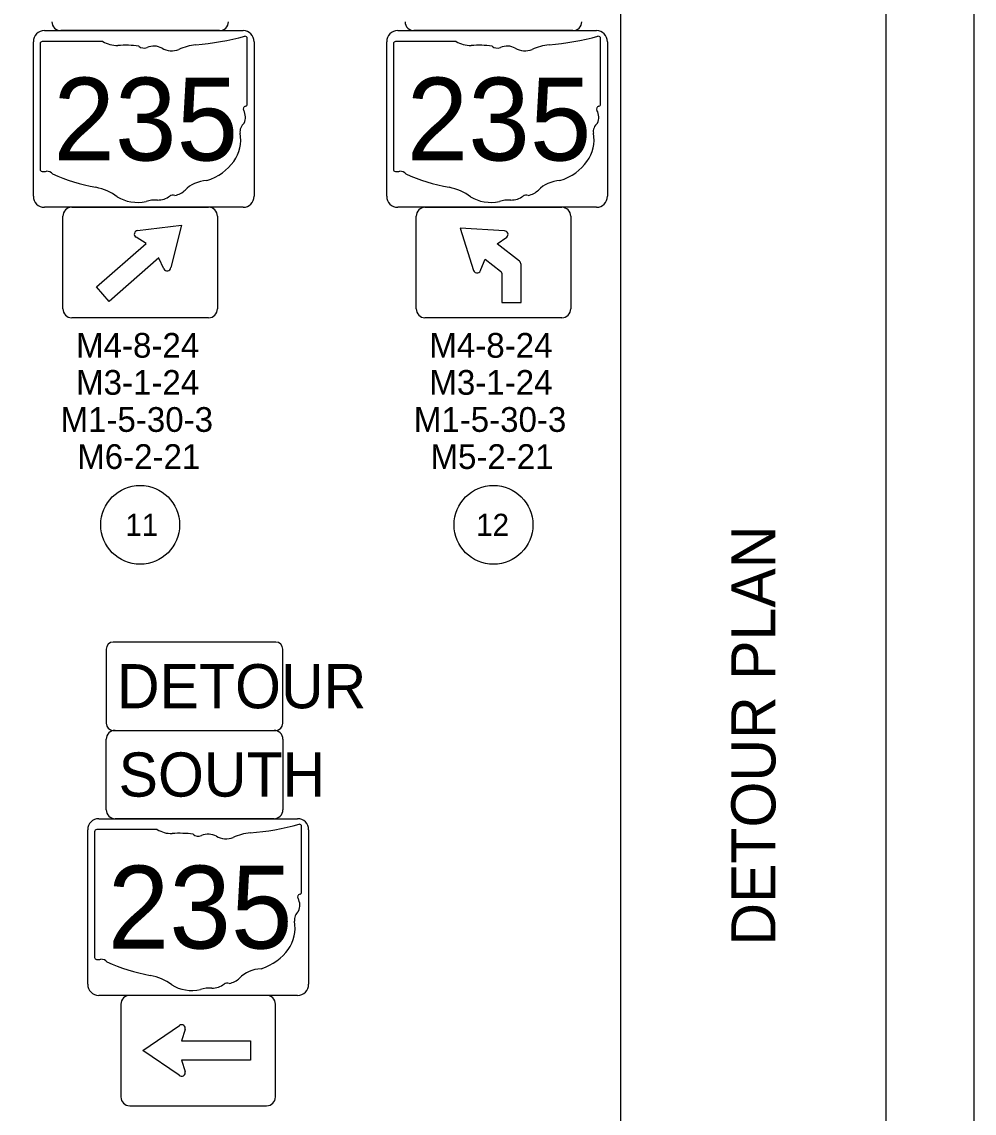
# Model space of a CAD drawing. Extents: x 632.2 to 666.2, y -36.3 to -14.3.
# Drawn here: x 660.8 to 666.19, y -25.48 to -19.3 of the extents above; entities that cross this region are included whole.
import ezdxf

# ---------------------------------------------------------------- set-up
doc = ezdxf.new("R2010")
doc.units = 0
for name, color, linetype in [('Default', 7, 'Continuous'), ('SH_Border', 7, 'Continuous'), ('SH_Cut_Line', 7, 'Continuous'), ('SH_Data', 7, 'Continuous'), ('SN_P_Signs', 7, 'Continuous'), ('SN_P_Text', 7, 'Continuous')]:
    doc.layers.add(name, color=color, linetype=linetype)

msp = doc.modelspace()

# ---------------------------------------------------------------- linework, layer by layer
at = {"layer": 'Default'}
for centre in [(661.466, -22.1449), (663.466, -22.1449)]:
    msp.add_circle(centre, 0.2232, dxfattribs=at)
at = {"layer": 'SH_Border'}
msp.add_line((664.1875, -35.8023), (664.1875, -14.8023), dxfattribs=at)
msp.add_lwpolyline([(633.6875, -14.8023), (665.6875, -14.8023), (665.6875, -35.8023), (633.6875, -35.8023)], close=True, dxfattribs=at)
at = {"layer": 'SH_Cut_Line'}
msp.add_lwpolyline([(632.1875, -36.3023), (666.1875, -36.3023), (666.1875, -14.3023), (632.1875, -14.3023)], close=True, dxfattribs=at)
at = {"layer": 'SN_P_Signs'}
for p, q in [((661.916, -19.3475), (661.016, -19.3475)), ((662.0725, -19.7634), (662.0725, -19.3912)), ((663.916, -19.3475), (663.016, -19.3475)), ((664.0725, -19.7634), (664.0725, -19.3912)), ((660.9006, -19.421), (660.9006, -20.1326)), ((661.2553, -19.4088), (660.9121, -19.4088)), ((662.9006, -19.421), (662.9006, -20.1326)), ((663.2553, -19.4088), (662.9121, -19.4088)), ((662.0723, -19.7633), (662.0725, -19.7634)), ((664.0723, -19.7633), (664.0725, -19.7634)), ((661.0785, -20.3475), (661.8535, -20.3475)), ((663.0785, -20.3475), (663.8535, -20.3475)), ((661.0285, -20.9225), (661.0285, -20.3975)), ((661.451, -20.4786), (661.7004, -20.449)), ((661.7004, -20.449), (661.6392, -20.6886)), ((661.9035, -20.3975), (661.9035, -20.9225)), ((663.0285, -20.9225), (663.0285, -20.3975)), ((663.9035, -20.3975), (663.9035, -20.9225)), ((661.451, -20.4786), (661.451, -20.4786)), ((663.529, -20.4809), (663.2785, -20.4654)), ((663.2785, -20.4654), (663.3539, -20.7049)), ((663.5291, -20.4809), (663.529, -20.4809)), ((661.2189, -20.7986), (661.4999, -20.5522)), ((661.4999, -20.5522), (661.4426, -20.5171)), ((663.4869, -20.5541), (663.5425, -20.5165)), ((663.6131, -20.653), (663.4869, -20.5541)), ((661.572, -20.6344), (661.2911, -20.8808)), ((661.5993, -20.6958), (661.572, -20.6345)), ((663.3947, -20.6986), (663.4194, -20.6404)), ((663.4194, -20.6404), (663.5067, -20.7088)), ((663.6222, -20.8865), (663.6222, -20.6715)), ((663.5129, -20.7212), (663.5129, -20.8865)), ((661.2911, -20.8808), (661.2189, -20.7986)), ((663.5129, -20.8865), (663.6222, -20.8865)), ((661.8535, -20.9725), (661.0785, -20.9725)), ((663.8535, -20.9725), (663.0785, -20.9725)), ((661.3238, -23.3085), (662.2238, -23.3085)), ((661.2738, -23.7585), (661.2738, -23.3585)), ((662.2738, -23.3585), (662.2738, -23.7585)), ((662.2238, -23.8085), (661.3238, -23.8085)), ((661.2084, -23.8821), (661.2084, -24.5936)), ((661.5631, -23.8698), (661.2199, -23.8698)), ((662.3803, -24.2244), (662.3803, -23.8522)), ((662.3801, -24.2243), (662.3803, -24.2244)), ((662.1819, -24.8085), (661.4069, -24.8085)), ((662.182, -24.8085), (662.1819, -24.8085)), ((661.3569, -24.8585), (661.3569, -25.3835)), ((662.2319, -25.3835), (662.2319, -24.8585)), ((661.4819, -25.121), (661.6888, -24.9788)), ((661.7205, -25.0021), (661.7006, -25.0663)), ((661.7006, -25.0663), (662.0912, -25.0663)), ((662.0912, -25.0663), (662.0912, -25.1757)), ((661.6859, -25.2607), (661.4819, -25.121)), ((662.0912, -25.1757), (661.7006, -25.1757)), ((661.7006, -25.1757), (661.7205, -25.2398)), ((661.4069, -25.4335), (662.1819, -25.4335))]:
    msp.add_line(p, q, dxfattribs=at)
for points in [[(660.9241, -19.3475), (662.0491, -19.3475)], [(662.9241, -19.3475), (664.0491, -19.3475)], [(660.8616, -20.285), (660.8616, -19.41)], [(662.1116, -19.41), (662.1116, -20.285)], [(662.8616, -20.285), (662.8616, -19.41)], [(664.1116, -19.41), (664.1116, -20.285)], [(662.0491, -20.3475), (660.9241, -20.3475)], [(664.0491, -20.3475), (662.9241, -20.3475)], [(661.2738, -22.8485), (661.2738, -23.2685)], [(662.2338, -22.8085), (661.3138, -22.8085)], [(662.2738, -23.2685), (662.2738, -22.8485)], [(661.3138, -23.3085), (662.2338, -23.3085)], [(661.2319, -23.8085), (662.3569, -23.8085)], [(661.1694, -24.746), (661.1694, -23.871)], [(662.4194, -23.871), (662.4194, -24.746)], [(662.3569, -24.8085), (661.2319, -24.8085)]]:
    msp.add_lwpolyline(points, dxfattribs=at)
for centre, radius, start, end in [((661.016, -19.2975), 0.05, 180, 270), ((661.916, -19.2975), 0.05, 270, 0), ((663.016, -19.2975), 0.05, 180, 270), ((663.916, -19.2975), 0.05, 270, 0), ((660.9241, -19.41), 0.0625, 90, 180), ((662.0491, -19.41), 0.0625, 0, 90), ((662.9241, -19.41), 0.0625, 90, 180), ((664.0491, -19.41), 0.0625, 0, 90), ((660.9241, -20.285), 0.0625, 180, 270), ((662.0491, -20.285), 0.0625, 270, 0), ((662.9241, -20.285), 0.0625, 180, 270), ((664.0491, -20.285), 0.0625, 270, 0), ((661.0785, -20.3974), 0.05, 90, 180), ((661.8535, -20.3974), 0.05, 0, 90), ((663.0785, -20.3975), 0.05, 90, 180), ((663.8535, -20.3975), 0.05, 0, 90), ((661.4535, -20.4993), 0.0209, 96.66992, 238.46331), ((663.5277, -20.5017), 0.0209, 314.99986, 86.40007), ((661.6183, -20.6873), 0.0209, 204.05409, 356.26826), ((663.5987, -20.6714), 0.0234, 0, 52.21426), ((663.3738, -20.6986), 0.0209, 197.41965, 359.94909), ((663.4972, -20.7212), 0.0156, 0, 52.65065), ((661.0785, -20.9224), 0.05, 180, 270), ((661.8535, -20.9224), 0.05, 270, 0), ((663.0785, -20.9225), 0.05, 180, 270), ((663.8535, -20.9225), 0.05, 270, 0), ((661.3138, -22.8485), 0.04, 90, 180), ((662.2338, -22.8485), 0.04, 0, 90), ((661.3138, -23.2685), 0.04, 180, 270), ((662.2338, -23.2685), 0.04, 270, 0), ((661.3238, -23.3585), 0.05, 90, 180), ((662.2238, -23.3585), 0.05, 0, 90), ((661.3238, -23.7585), 0.05, 180, 270), ((662.2238, -23.7585), 0.05, 270, 0), ((661.2319, -23.871), 0.0625, 90, 180), ((662.3569, -23.871), 0.0625, 0, 90), ((661.2319, -24.746), 0.0625, 180, 270), ((662.3569, -24.746), 0.0625, 270, 0), ((661.4069, -24.8585), 0.05, 90, 180), ((662.1819, -24.8585), 0.05, 0, 90), ((661.7007, -24.996), 0.0209, 342.79539, 124.58878), ((661.7007, -25.246), 0.0209, 224.99044, 17.20461), ((661.4069, -25.3835), 0.05, 180, 270), ((662.1819, -25.3835), 0.05, 270, 0)]:
    msp.add_arc(centre, radius, start, end, dxfattribs=at)
for centre, major_axis, start_param, end_param in [((661.655, -18.4387), (1.2427, 0), 4.814394, 5.042369), ((662.0595, -19.3896), (0.013, 0), 6.141152, 7.989035), ((663.655, -18.4387), (1.2427, 0), 4.814394, 5.042369), ((664.0595, -19.3896), (0.013, 0), 6.141152, 7.989035), ((660.914, -19.4195), (0.0136, 0), 1.712693, 3.28349), ((661.337, -19.3262), (0.1317, 0), 4.042523, 4.731795), ((661.3807, -19.8083), (0.4727, 0), 1.404758, 1.657858), ((661.488, -19.4158), (0.038, 0), 3.836095, 5.185415), ((661.5438, -19.4981), (0.079, 0), 0.950623, 2.079405), ((661.6457, -19.3853), (0.095, 0), 4.081561, 5.145723), ((661.8135, -19.6261), (0.25, 0), 1.699011, 2.107814), ((662.914, -19.4195), (0.0136, 0), 1.712693, 3.28349), ((663.337, -19.3262), (0.1317, 0), 4.042523, 4.731795), ((663.3807, -19.8083), (0.4727, 0), 1.404758, 1.657858), ((663.488, -19.4158), (0.038, 0), 3.836095, 5.185415), ((663.5438, -19.4981), (0.079, 0), 0.950623, 2.079405), ((663.6457, -19.3853), (0.095, 0), 4.081561, 5.145723), ((663.8135, -19.6261), (0.25, 0), 1.699011, 2.107814), ((662.0585, -19.7648), (0.014, 0), 5.05454, 6.418171), ((664.0585, -19.7648), (0.014, 0), 5.05454, 6.418171), ((662.0694, -19.7907), (0.0202, 0), 1.883978, 3.671073), ((661.941, -19.8378), (0.1212, 0), 5.934695, 6.695948), ((664.0694, -19.7907), (0.0202, 0), 1.883978, 3.671073), ((663.941, -19.8378), (0.1212, 0), 5.934695, 6.695948), ((662.1192, -19.9192), (0.0882, 0), 2.387724, 3.262537), ((664.1192, -19.9192), (0.0882, 0), 2.387724, 3.262537), ((661.7246, -19.9665), (0.3108, 0), 5.101752, 6.440018), ((663.7246, -19.9665), (0.3108, 0), 5.101752, 6.440018), ((660.9141, -20.1341), (0.0137, 0), 3.00124, 4.508301), ((662.9141, -20.1341), (0.0137, 0), 3.00124, 4.508301), ((660.9162, -20.0613), (0.1045, 0), 4.665946, 4.897461), ((660.9376, -20.1736), (0.0377, 0), 0.519207, 1.627899), ((661.4134, -19.5343), (0.8974, 0), 4.195997, 4.488961), ((661.8557, -20.3323), (0.1702, 0), 1.647645, 2.488434), ((662.9162, -20.0613), (0.1045, 0), 4.665946, 4.897461), ((662.9376, -20.1736), (0.0377, 0), 0.519207, 1.627899), ((663.4134, -19.5343), (0.8974, 0), 4.195997, 4.488961), ((663.8557, -20.3323), (0.1702, 0), 1.647645, 2.488434), ((661.1459, -20.4522), (0.2808, 0), 0.823519, 1.323587), ((661.64, -20.2015), (0.1004, 0), 4.937069, 5.64225), ((663.1459, -20.4522), (0.2808, 0), 0.823519, 1.323587), ((663.64, -20.2015), (0.1004, 0), 4.937069, 5.64225), ((661.4496, -20.1772), (0.1782, 0), 4.026481, 4.996735), ((661.5525, -20.4232), (0.1464, 0), 1.495662, 1.94098), ((661.5655, -20.2304), (0.0949, 0), 4.691044, 5.507374), ((661.6514, -20.2994), (0.0267, 0), 1.147584, 2.315152), ((663.4496, -20.1772), (0.1782, 0), 4.026481, 4.996735), ((663.5525, -20.4232), (0.1464, 0), 1.495662, 1.94098), ((663.5655, -20.2304), (0.0949, 0), 4.691044, 5.507374), ((663.6514, -20.2994), (0.0267, 0), 1.147584, 2.315152), ((661.9628, -22.8997), (1.2427, 0), 4.814394, 5.042369), ((662.3673, -23.8506), (0.013, 0), 6.141152, 7.989035), ((661.2218, -23.8805), (0.0136, 0), 1.712693, 3.28349), ((661.6449, -23.7872), (0.1317, 0), 4.042523, 4.731795), ((661.6885, -24.2693), (0.4727, 0), 1.404758, 1.657858), ((661.7958, -23.8769), (0.038, 0), 3.836095, 5.185415), ((661.8516, -23.9591), (0.079, 0), 0.950623, 2.079405), ((661.9535, -23.8463), (0.095, 0), 4.081561, 5.145723), ((662.1213, -24.0871), (0.25, 0), 1.699011, 2.107814), ((662.3772, -24.2517), (0.0202, 0), 1.883978, 3.671073), ((662.2488, -24.2988), (0.1212, 0), 5.934695, 6.695948), ((662.3663, -24.2258), (0.014, 0), 5.05454, 6.418171), ((662.427, -24.3802), (0.0882, 0), 2.387724, 3.262537), ((662.0324, -24.4275), (0.3108, 0), 5.101752, 6.440018), ((661.222, -24.5952), (0.0137, 0), 3.00124, 4.508301), ((661.224, -24.5224), (0.1045, 0), 4.665946, 4.897461), ((661.2454, -24.6346), (0.0377, 0), 0.519207, 1.627899), ((661.7212, -23.9954), (0.8974, 0), 4.195997, 4.488961), ((661.4537, -24.9133), (0.2808, 0), 0.823519, 1.323587), ((661.9478, -24.6626), (0.1004, 0), 4.937069, 5.64225), ((662.1635, -24.7934), (0.1702, 0), 1.647645, 2.488434), ((661.7574, -24.6382), (0.1782, 0), 4.026481, 4.996735), ((661.8603, -24.8842), (0.1464, 0), 1.495662, 1.94098), ((661.8733, -24.6915), (0.0949, 0), 4.691044, 5.507374), ((661.9592, -24.7604), (0.0267, 0), 1.147584, 2.315152)]:
    msp.add_ellipse(centre, major_axis=major_axis, ratio=0.8, start_param=start_param, end_param=end_param, dxfattribs=at)

# ---------------------------------------------------------------- texts
at = {"layer": 'Default'}
for s, p in [('11', (661.3821, -22.2074)), ('12', (663.3684, -22.2074))]:
    msp.add_text(s, height=0.125, dxfattribs=at).set_placement(p)
at = {"layer": 'SH_Data'}
msp.add_text('DETOUR PLAN', height=0.25, rotation=90, dxfattribs=at).set_placement((665.0625, -24.5271))
at = {"layer": 'SN_P_Signs'}
for s, height, p in [('235', 0.46875, (660.9748, -20.0824)), ('235', 0.46875, (662.9748, -20.0824)), ('DETOUR', 0.25, (661.3346, -23.1835)), ('SOUTH', 0.25, (661.3438, -23.6835)), ('235', 0.46875, (661.2826, -24.5434))]:
    msp.add_text(s, height=height, dxfattribs=at).set_placement(p)
at = {"layer": 'SN_P_Text'}
for s, p in [('M4-8-24', (661.1032, -21.1987)), ('M4-8-24', (663.1032, -21.1987)), ('M3-1-24', (661.1032, -21.4087)), ('M3-1-24', (663.1032, -21.4087)), ('M1-5-30-3', (661.015, -21.6187)), ('M1-5-30-3', (663.015, -21.6187)), ('M6-2-21', (661.1095, -21.8287)), ('M5-2-21', (663.1095, -21.8287))]:
    msp.add_text(s, height=0.14, dxfattribs=at).set_placement(p)

doc.saveas('drawing.dxf')
